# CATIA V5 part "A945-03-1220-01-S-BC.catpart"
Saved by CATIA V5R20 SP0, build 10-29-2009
Part number: A945-03-1220-01-S-BC
Source: Unknown
Property "ARTICLENO": "A945-03-1220-01-S-BC"
Property "B": "125.000"
Property "BOMINFO": "A945-03-1220-01-S-BC"
Property "CODE": "A945-03-1220-01-S-BC"
Property "D1": "26.000"
Property "D2": "17.500"
Property "D5": "20.000"
Property "D6": "16.000"
Property "H": "57.000"
Property "H1": "44.000"
Property "H2": "60.000"
Property "H3": "28.000"
Property "L1": "200.000"
Property "L2": "25.000"
Property "L3": "0.000"
Property "L4": "150.000"
Property "L5": "55.000"
Property "L6": "95.000"
Property "LINA": "A945-03-1220-01-S-BC"
Property "N": "6.000"
Property "NB": "A945-03-1220-01-S-BC"
Property "NBSYN": "$CODE."
Property "NN": "A945-03"
Property "NT": "v driver sets replaceable inserts pisitive return"
Property "SUPPLIER": "CF"
Property "Z": "85.000"
Bounding box of the stored display mesh (mm): x -669.473 to -511.473, y 748.188 to 833.188, z 0 to 200
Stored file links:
  C:\Users\Utente\Desktop\3D files A945-03\A945-03-1220-01-S-BC.catpart
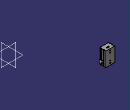
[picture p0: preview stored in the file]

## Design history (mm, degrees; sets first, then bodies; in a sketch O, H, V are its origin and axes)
Body1 "Geometry.1" (main body)
  Solid1 "A945-03-1220-01-S-BC.catpart": solid without history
